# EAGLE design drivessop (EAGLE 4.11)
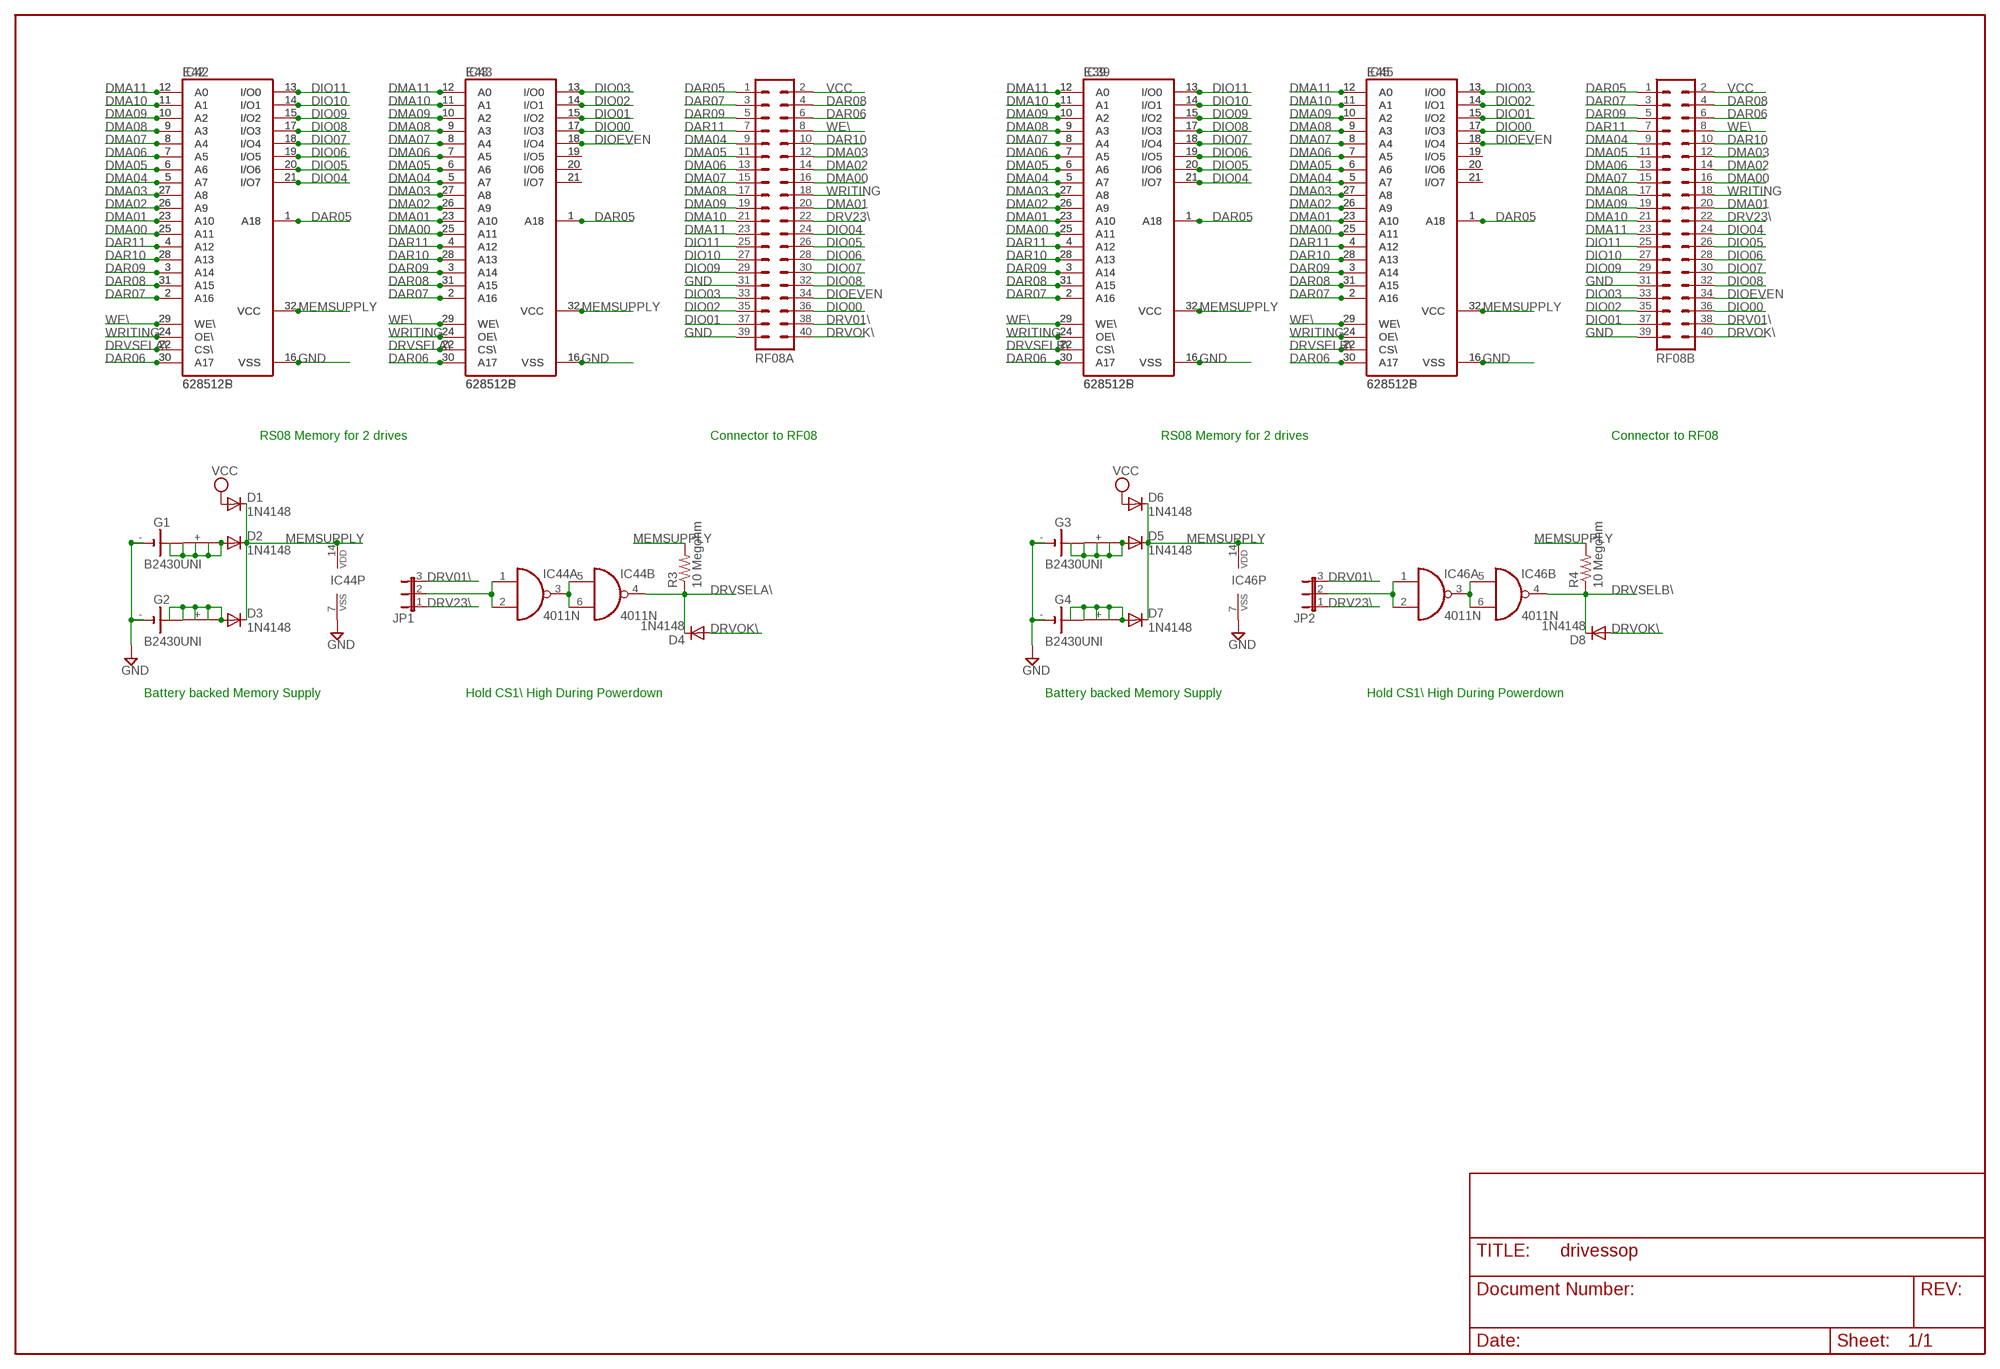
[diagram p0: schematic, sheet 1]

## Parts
D1  1N4148  [DO35-10]
D2  1N4148  [DO35-10]
D3  1N4148  [DO35-10]
D4  1N4148  [DO35-10]
D5  1N4148  [DO35-10]
D6  1N4148  [DO35-10]
D7  1N4148  [DO35-10]
D8  1N4148  [DO35-10]
E39  628512S  [S032L]
E42  628512S  [S032L]
E43  628512S  [S032L]
E45  628512S  [S032L]
G1  B2430UNI  [B2430UNI]
G2  B2430UNI  [B2430UNI]
G3  B2430UNI  [B2430UNI]
G4  B2430UNI  [B2430UNI]
IC39  628512P  [DIL32]
IC42  628512P  [DIL32]
IC43  628512P  [DIL32]
IC44  4011N  [DIL14]
IC45  628512P  [DIL32]
IC46  4011N  [DIL14]
JP1  JP2E  [JP2]
JP2  JP2E  [JP2]
R3  10 Megohm  R-US_0207/10  [0207/10]
R4  10 Megohm  R-US_0207/10  [0207/10]
RF08A  MA20-2  [MA20-2]
RF08B  MA20-2  [MA20-2]

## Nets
DAR05: E39.1(A18) E42.1(A18) E43.1(A18) E45.1(A18) IC39.1(A18) IC42.1(A18) IC43.1(A18) IC45.1(A18) RF08A.1 RF08B.1
DAR06: E39.30(A17) E42.30(A17) E43.30(A17) E45.30(A17) IC39.30(A17) IC42.30(A17) IC43.30(A17) IC45.30(A17) RF08A.6 RF08B.6
DAR07: E39.2(A16) E42.2(A16) E43.2(A16) E45.2(A16) IC39.2(A16) IC42.2(A16) IC43.2(A16) IC45.2(A16) RF08A.3 RF08B.3
DAR08: E39.31(A15) E42.31(A15) E43.31(A15) E45.31(A15) IC39.31(A15) IC42.31(A15) IC43.31(A15) IC45.31(A15) RF08A.4 RF08B.4
DAR09: E39.3(A14) E42.3(A14) E43.3(A14) E45.3(A14) IC39.3(A14) IC42.3(A14) IC43.3(A14) IC45.3(A14) RF08A.5 RF08B.5
DAR10: E39.28(A13) E42.28(A13) E43.28(A13) E45.28(A13) IC39.28(A13) IC42.28(A13) IC43.28(A13) IC45.28(A13) RF08A.10 RF08B.10
DAR11: E39.4(A12) E42.4(A12) E43.4(A12) E45.4(A12) IC39.4(A12) IC42.4(A12) IC43.4(A12) IC45.4(A12) RF08A.7 RF08B.7
DIO00: E43.17(I/O3) E45.17(I/O3) IC43.17(I/O3) IC45.17(I/O3) RF08A.36 RF08B.36
DIO01: E43.15(I/O2) E45.15(I/O2) IC43.15(I/O2) IC45.15(I/O2) RF08A.37 RF08B.37
DIO02: E43.14(I/O1) E45.14(I/O1) IC43.14(I/O1) IC45.14(I/O1) RF08A.35 RF08B.35
DIO03: E43.13(I/O0) E45.13(I/O0) IC43.13(I/O0) IC45.13(I/O0) RF08A.33 RF08B.33
DIO04: E39.21(I/O7) E42.21(I/O7) IC39.21(I/O7) IC42.21(I/O7) RF08A.24 RF08B.24
DIO05: E39.20(I/O6) E42.20(I/O6) IC39.20(I/O6) IC42.20(I/O6) RF08A.26 RF08B.26
DIO06: E39.19(I/O5) E42.19(I/O5) IC39.19(I/O5) IC42.19(I/O5) RF08A.28 RF08B.28
DIO07: E39.18(I/O4) E42.18(I/O4) IC39.18(I/O4) IC42.18(I/O4) RF08A.30 RF08B.30
DIO08: E39.17(I/O3) E42.17(I/O3) IC39.17(I/O3) IC42.17(I/O3) RF08A.32 RF08B.32
DIO09: E39.15(I/O2) E42.15(I/O2) IC39.15(I/O2) IC42.15(I/O2) RF08A.29 RF08B.29
DIO10: E39.14(I/O1) E42.14(I/O1) IC39.14(I/O1) IC42.14(I/O1) RF08A.27 RF08B.27
DIO11: E39.13(I/O0) E42.13(I/O0) IC39.13(I/O0) IC42.13(I/O0) RF08A.25 RF08B.25
DIOEVEN: E43.18(I/O4) E45.18(I/O4) IC43.18(I/O4) IC45.18(I/O4) RF08A.34 RF08B.34
DMA00: E39.25(A11) E42.25(A11) E43.25(A11) E45.25(A11) IC39.25(A11) IC42.25(A11) IC43.25(A11) IC45.25(A11) RF08A.16 RF08B.16
DMA01: E39.23(A10) E42.23(A10) E43.23(A10) E45.23(A10) IC39.23(A10) IC42.23(A10) IC43.23(A10) IC45.23(A10) RF08A.20 RF08B.20
DMA02: E39.26(A9) E42.26(A9) E43.26(A9) E45.26(A9) IC39.26(A9) IC42.26(A9) IC43.26(A9) IC45.26(A9) RF08A.14 RF08B.14
DMA03: E39.27(A8) E42.27(A8) E43.27(A8) E45.27(A8) IC39.27(A8) IC42.27(A8) IC43.27(A8) IC45.27(A8) RF08A.12 RF08B.12
DMA04: E39.5(A7) E42.5(A7) E43.5(A7) E45.5(A7) IC39.5(A7) IC42.5(A7) IC43.5(A7) IC45.5(A7) RF08A.9 RF08B.9
DMA05: E39.6(A6) E42.6(A6) E43.6(A6) E45.6(A6) IC39.6(A6) IC42.6(A6) IC43.6(A6) IC45.6(A6) RF08A.11 RF08B.11
DMA06: E39.7(A5) E42.7(A5) E43.7(A5) E45.7(A5) IC39.7(A5) IC42.7(A5) IC43.7(A5) IC45.7(A5) RF08A.13 RF08B.13
DMA07: E39.8(A4) E42.8(A4) E43.8(A4) E45.8(A4) IC39.8(A4) IC42.8(A4) IC43.8(A4) IC45.8(A4) RF08A.15 RF08B.15
DMA08: E39.9(A3) E42.9(A3) E43.9(A3) E45.9(A3) IC39.9(A3) IC42.9(A3) IC43.9(A3) IC45.9(A3) RF08A.17 RF08B.17
DMA09: E39.10(A2) E42.10(A2) E43.10(A2) E45.10(A2) IC39.10(A2) IC42.10(A2) IC43.10(A2) IC45.10(A2) RF08A.19 RF08B.19
DMA10: E39.11(A1) E42.11(A1) E43.11(A1) E45.11(A1) IC39.11(A1) IC42.11(A1) IC43.11(A1) IC45.11(A1) RF08A.21 RF08B.21
DMA11: E39.12(A0) E42.12(A0) E43.12(A0) E45.12(A0) IC39.12(A0) IC42.12(A0) IC43.12(A0) IC45.12(A0) RF08A.23 RF08B.23
DRV01\: JP1.3 JP2.3 RF08A.38 RF08B.38
DRV23\: JP1.1 JP2.1 RF08A.22 RF08B.22
DRVOK\: D4.A D8.A RF08A.40 RF08B.40
DRVSELA\: D4.C E42.22(CS\) E43.22(CS\) IC42.22(CS\) IC43.22(CS\) IC44.4(B:O) R3.1
DRVSELB\: D8.C E39.22(CS\) E45.22(CS\) IC39.22(CS\) IC45.22(CS\) IC46.4(B:O) R4.1
GND: E39.16(VSS) E42.16(VSS) E43.16(VSS) E45.16(VSS) G1.- G1.-@1(-) G2.- G2.-@1(-) G3.- G3.-@1(-) G4.- G4.-@1(-) IC39.16(VSS) IC42.16(VSS) IC43.16(VSS) IC44.7(P:VSS) IC45.16(VSS) IC46.7(P:VSS) RF08A.31 RF08A.39 RF08B.31 RF08B.39
MEMSUPPLY [Power]: D1.C D2.C D3.C D5.C D6.C D7.C E39.32(VCC) E42.32(VCC) E43.32(VCC) E45.32(VCC) IC39.32(VCC) IC42.32(VCC) IC43.32(VCC) IC44.14(P:VDD) IC45.32(VCC) IC46.14(P:VDD) R3.2 R4.2
N$1: E43.19(I/O5) IC43.19(I/O5)
N$2: E43.20(I/O6) IC43.20(I/O6)
N$3: E43.21(I/O7) IC43.21(I/O7)
N$4: E45.19(I/O5) IC45.19(I/O5)
N$5: E45.20(I/O6) IC45.20(I/O6)
N$6: E45.21(I/O7) IC45.21(I/O7)
N$18: IC44.3(A:O) IC44.5(B:I0) IC44.6(B:I1)
N$35: IC44.1(A:I0) IC44.2(A:I1) JP1.2
N$36: D7.A G4.+ G4.+@1(+) G4.+@2(+) G4.+@3(+) G4.+@4(+)
N$38: IC46.3(A:O) IC46.5(B:I0) IC46.6(B:I1)
N$39: IC46.1(A:I0) IC46.2(A:I1) JP2.2
N$41: D5.A G3.+ G3.+@1(+) G3.+@2(+) G3.+@3(+) G3.+@4(+)
N$130: D3.A G2.+ G2.+@1(+) G2.+@2(+) G2.+@3(+) G2.+@4(+)
N$131: D2.A G1.+ G1.+@1(+) G1.+@2(+) G1.+@3(+) G1.+@4(+)
VCC [Power]: D1.A D6.A RF08A.2 RF08B.2
WE\: E39.29(WE\) E42.29(WE\) E43.29(WE\) E45.29(WE\) IC39.29(WE\) IC42.29(WE\) IC43.29(WE\) IC45.29(WE\) RF08A.8 RF08B.8
WRITING: E39.24(OE\) E42.24(OE\) E43.24(OE\) E45.24(OE\) IC39.24(OE\) IC42.24(OE\) IC43.24(OE\) IC45.24(OE\) RF08A.18 RF08B.18
Unconnected: IC44.8(C:I0) IC44.9(C:I1) IC44.10(C:O) IC44.11(D:O) IC44.12(D:I0) IC44.13(D:I1) IC46.8(C:I0) IC46.9(C:I1) IC46.10(C:O) IC46.11(D:O) IC46.12(D:I0) IC46.13(D:I1)

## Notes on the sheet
- RS08 Memory for 2 drives | Connector to RF08 | RS08 Memory for 2 drives | Connector to RF08
- Battery backed Memory Supply | Hold CS1\ High During Powerdown | Battery backed Memory Supply | Hold CS1\ High During Powerdown

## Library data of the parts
D1-D8 = diode:1N4148: DIODE
E39 E42 E43 E45 = memory-hitachi:628512S: 512Kx8 Static RAM
G1-G4 = battery:B2430UNI: LI BATTERY
IC39 IC42 IC43 IC45 = memory-hitachi:628512P: 512Kx8 Static RAM
IC44 IC46 = 40xx:4011: Quad 2-input NAND
JP1 JP2 = jumper:JP2E: JUMPER
R3 R4 = rcl:R-US_: RESISTOR, American symbol
RF08A RF08B = con-lstb:MA20-2: PIN HEADER

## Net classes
1 Power: width 0.508 mm

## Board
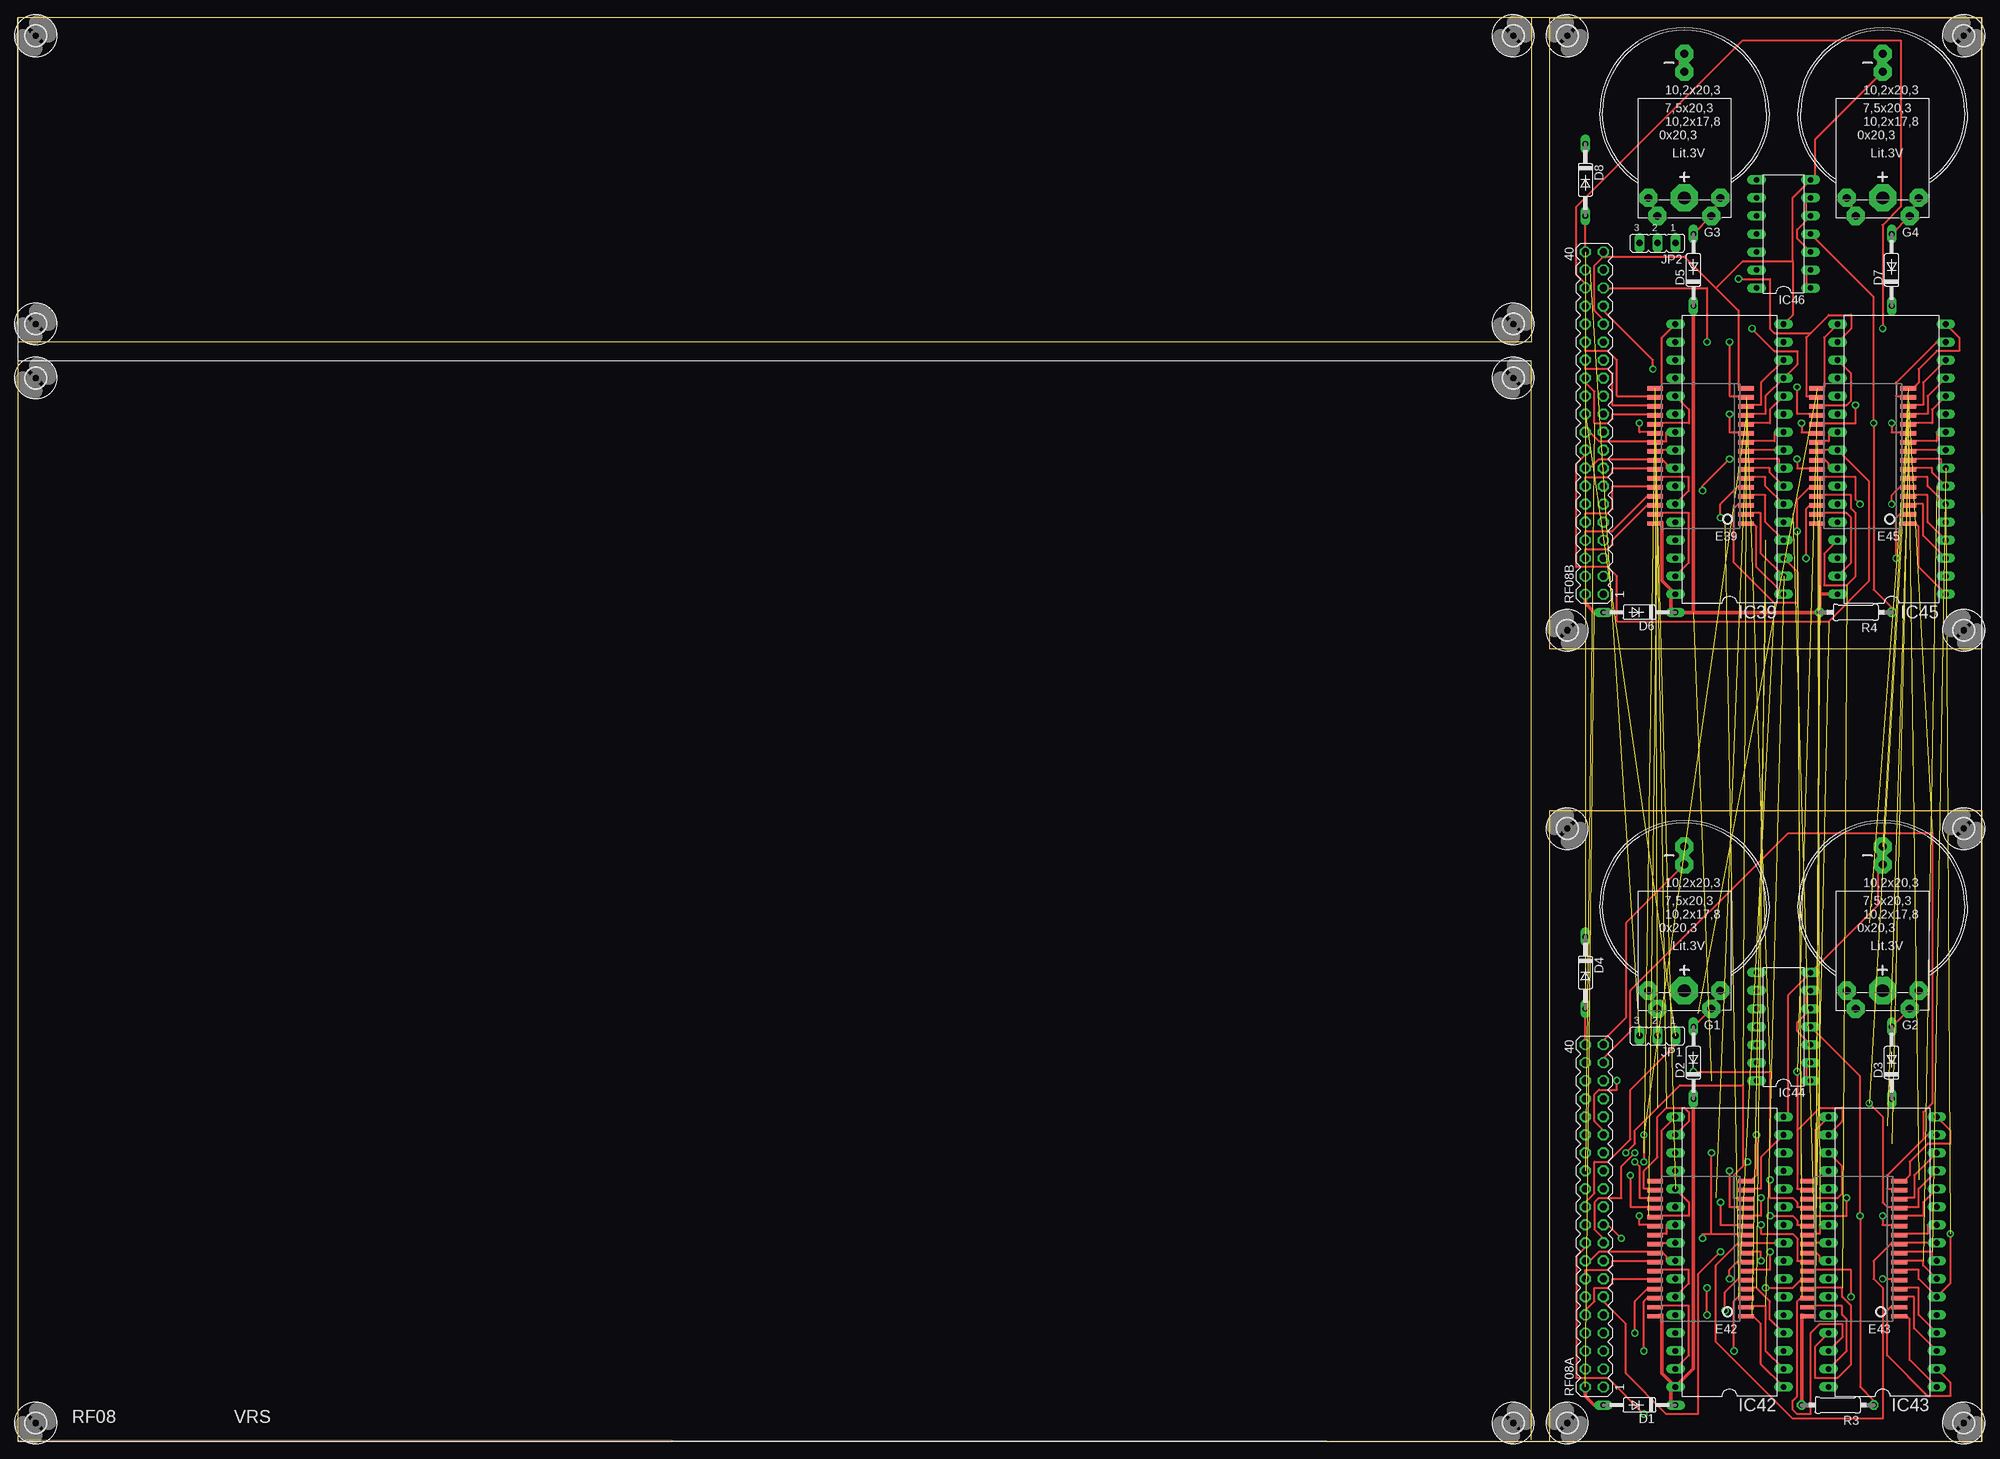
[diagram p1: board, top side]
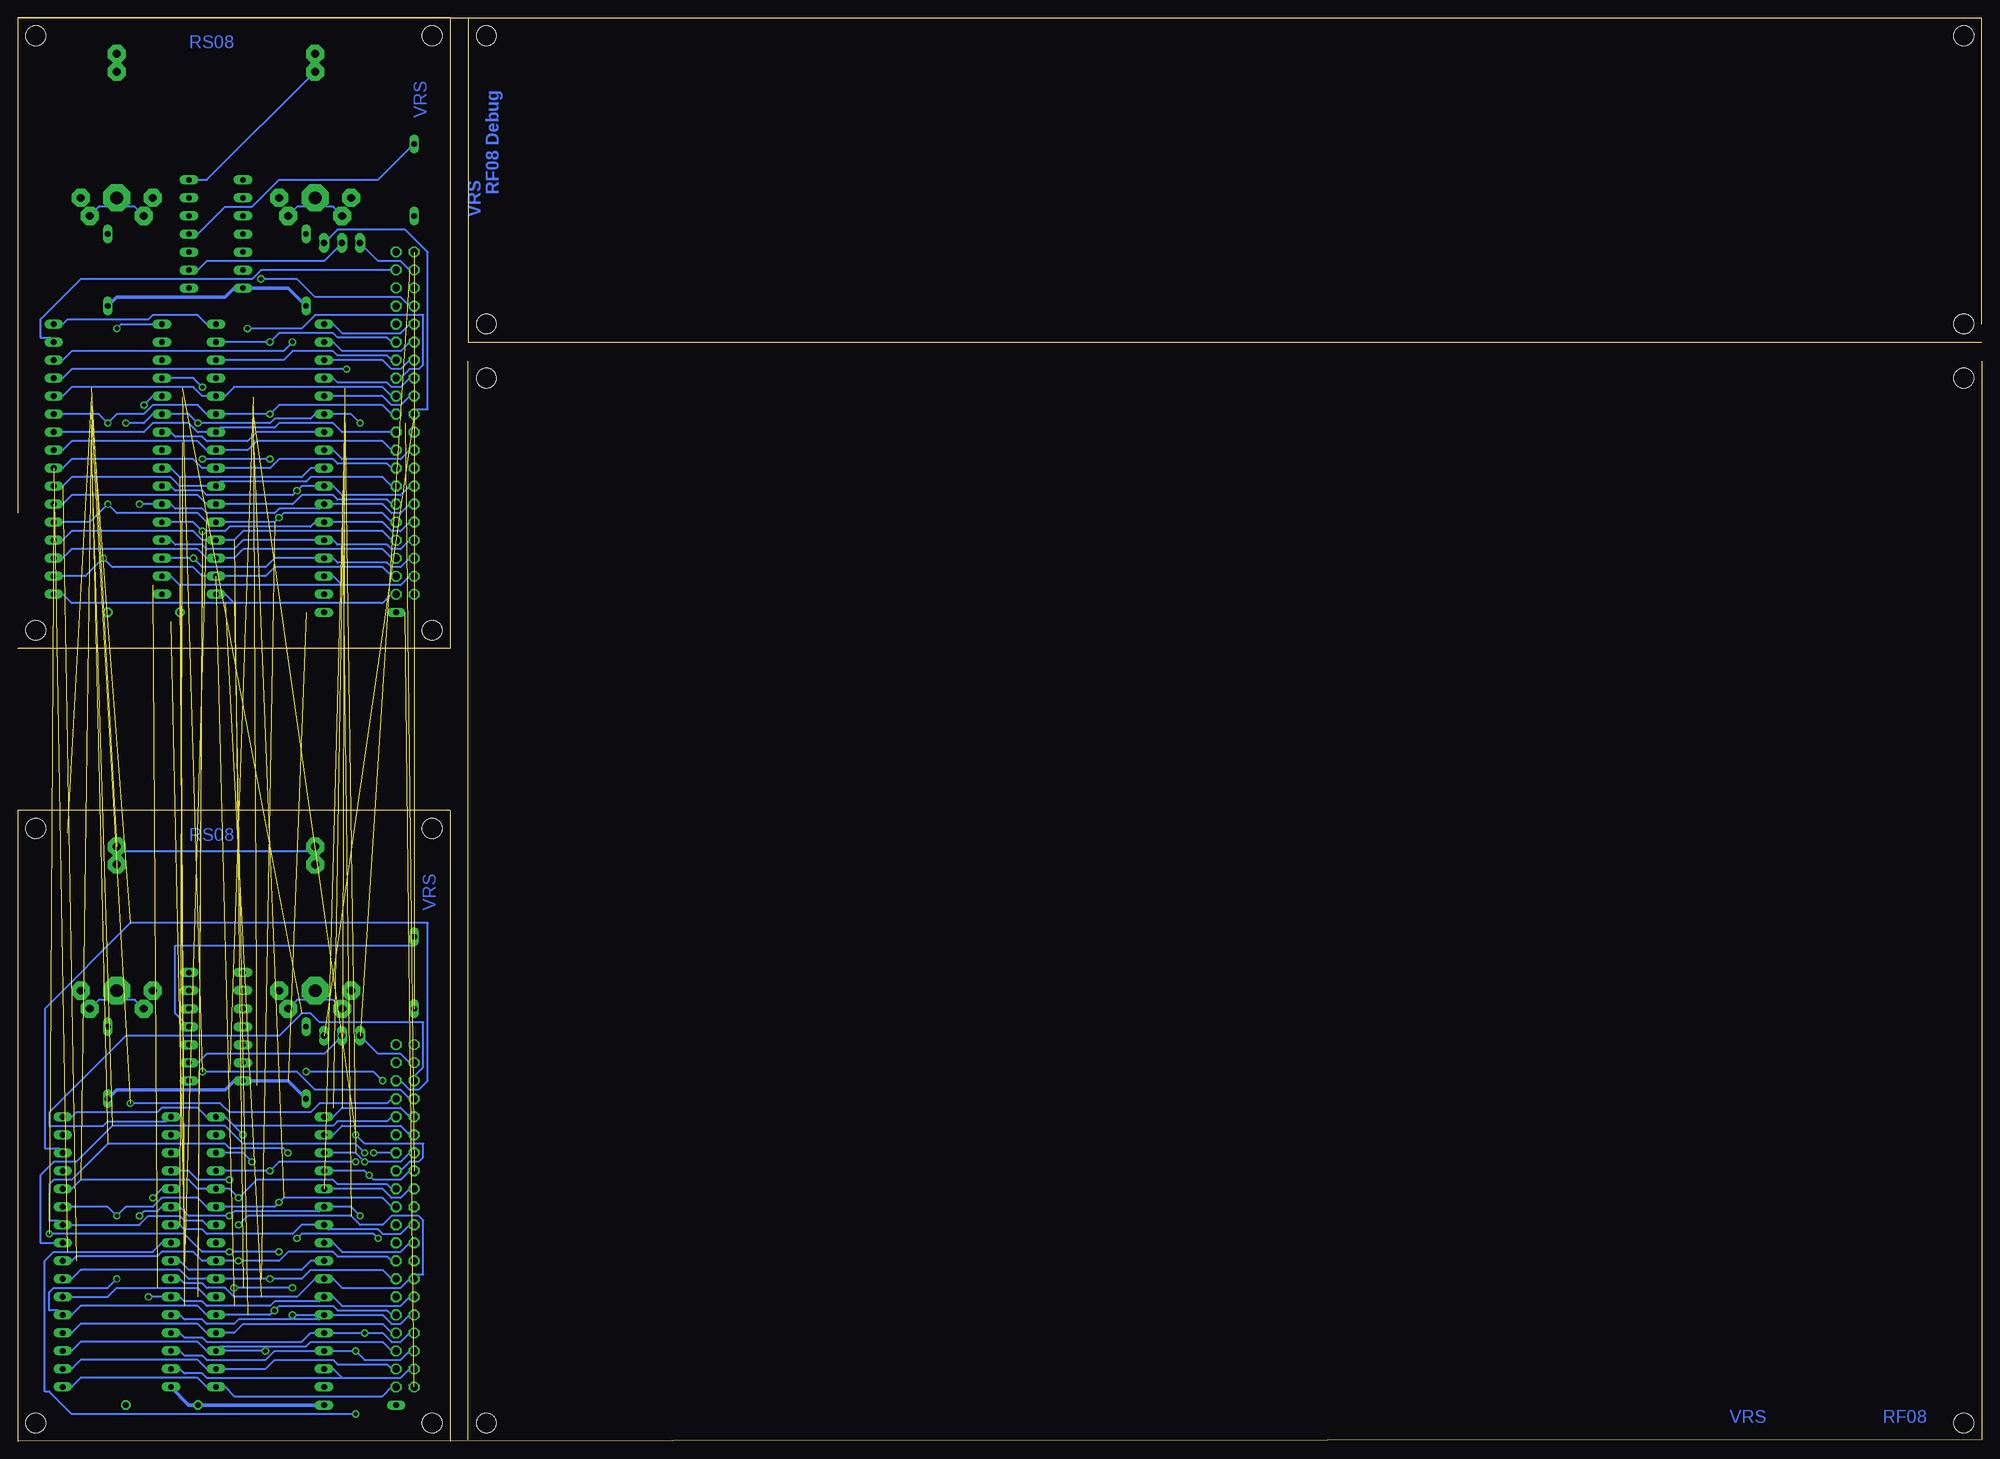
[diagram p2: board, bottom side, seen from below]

Size 276.86 x 200.67 mm. Coordinates in mm from the lower left corner, seen from the top.
Outline: 276.69,0 0.01,0.18 0.01,152.25
Outline: 213.34,0.18 213.34,152.25
Outline: 215.9,0.01 215.9,88.92 276.86,88.92 276.86,0.01
Outline: 276.86,111.78 215.9,111.78 215.9,200.67 276.86,200.67
Outline: 276.86,200.67 0,200.67 0,157.49
Outline: 276.86,200.67 276.86,130.82
Outline: 0,154.95 213.36,154.95 213.36,200.67
Copper layers (1*16): Top 0.035mm / dielectric 1.5mm / Bottom 0.035mm
Design rules "olimex10mil": minimum track width 10mil, minimum drill 24mil, track to track 10mil, track to pad 10mil, pad to pad 10mil, via to via 10mil, smd to smd 10mil, copper to edge 40mil, drill to drill 10mil, minimum pad ring 10mil, minimum via ring 8mil, stop-mask expansion 0mil, vias tented up to drill 0mil, thermal gap 10mil

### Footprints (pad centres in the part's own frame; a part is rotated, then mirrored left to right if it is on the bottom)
DO35-10 = drill 0.813 long: A 5.08,0; C -5.08,0
S032L = smd 0.6 x 2.2: 1 -7.795,-6.146; 2 -6.525,-6.146; 3 -5.255,-6.146; 4 -3.985,-6.146; 5 -2.715,-6.146; 6 -1.445,-6.146; 7 -0.175,-6.146; 8 1.095,-6.146; 9 2.365,-6.146; 10 3.635,-6.146; 11 4.905,-6.146; 12 6.175,-6.146; 13 7.445,-6.146; 14 8.715,-6.146; 15 9.985,-6.146; 16 11.255,-6.146; 17 11.255,6.686; 18 9.985,6.686; 19 8.715,6.686; 20 7.445,6.686; 21 6.175,6.686; 22 4.905,6.686; 23 3.635,6.686; 24 2.365,6.686; 25 1.095,6.686; 26 -0.175,6.686; 27 -1.445,6.686; 28 -2.715,6.686; 29 -3.985,6.686; 30 -5.255,6.686; 31 -6.525,6.686; 32 -7.795,6.686
B2430UNI = drill 1.118 pad 2.54 octagon: + 3.81,14.605; +@1 -3.81,14.605; +@2 -5.08,12.065; +@3 5.08,12.065; - 0,-5.715; -@1 0,-8.255 | drill 1.803 pad 3.81 octagon: +@4 0,12.065
DIL32 = drill 0.813 long: 1 -19.05,-7.62; 2 -16.51,-7.62; 3 -13.97,-7.62; 4 -11.43,-7.62; 5 -8.89,-7.62; 6 -6.35,-7.62; 7 -3.81,-7.62; 8 -1.27,-7.62; 9 1.27,-7.62; 10 3.81,-7.62; 11 6.35,-7.62; 12 8.89,-7.62; 13 11.43,-7.62; 14 13.97,-7.62; 15 16.51,-7.62; 16 19.05,-7.62; 17 19.05,7.62; 18 16.51,7.62; 19 13.97,7.62; 20 11.43,7.62; 21 8.89,7.62; 22 6.35,7.62; 23 3.81,7.62; 24 1.27,7.62; 25 -1.27,7.62; 26 -3.81,7.62; 27 -6.35,7.62; 28 -8.89,7.62; 29 -11.43,7.62; 30 -13.97,7.62; 31 -16.51,7.62; 32 -19.05,7.62
DIL14 = drill 0.813 long: 1 -7.62,-3.81; 2 -5.08,-3.81; 3 -2.54,-3.81; 4 0,-3.81; 5 2.54,-3.81; 6 5.08,-3.81; 7 7.62,-3.81; 8 7.62,3.81; 9 5.08,3.81; 10 2.54,3.81; 11 0,3.81; 12 -2.54,3.81; 13 -5.08,3.81; 14 -7.62,3.81
JP2 = drill 0.914 long: 1 -2.54,0; 2 0,0; 3 2.54,0
0207/10 = drill 0.813 octagon: 1 -5.08,0; 2 5.08,0
MA20-2 = drill 1.016 octagon: 1 -24.13,-1.27; 2 -24.13,1.27; 3 -21.59,-1.27; 4 -21.59,1.27; 5 -19.05,-1.27; 6 -19.05,1.27; 7 -16.51,-1.27; 8 -16.51,1.27; 9 -13.97,-1.27; 10 -13.97,1.27; 11 -11.43,-1.27; 12 -11.43,1.27; 13 -8.89,-1.27; 14 -8.89,1.27; 15 -6.35,-1.27; 16 -6.35,1.27; 17 -3.81,-1.27; 18 -3.81,1.27; 19 -1.27,-1.27; 20 -1.27,1.27; 21 1.27,-1.27; 22 1.27,1.27; 23 3.81,-1.27; 24 3.81,1.27; 25 6.35,-1.27; 26 6.35,1.27; 27 8.89,-1.27; 28 8.89,1.27; 29 11.43,-1.27; 30 11.43,1.27; 31 13.97,-1.27; 32 13.97,1.27; 33 16.51,-1.27; 34 16.51,1.27; 35 19.05,-1.27; 36 19.05,1.27; 37 21.59,-1.27; 38 21.59,1.27; 39 24.13,-1.27; 40 24.13,1.27
2,8 = hole 2.8: 0,0

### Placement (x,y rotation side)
D1  228.6,5.09 180 top
D2  236.22,53.36 90 top
D3  264.16,53.36 90 top
D4  220.98,66.06 270 top
D5  236.22,165.11 90 top
D6  228.6,116.86 180 top
D7  264.16,165.11 90 top
D8  220.98,177.81 270 top
E39  237.49,137.17 90 top
E42  237.49,25.41 90 top
E43  259.08,25.41 90 top
E45  260.35,137.17 90 top
G1  234.95,75.58 180 top
G2  262.89,75.58 180 top
G3  234.95,187.34 180 top
G4  262.89,187.34 180 top
IC39  241.3,138.44 90 top
IC42  241.3,26.69 90 top
IC43  262.89,26.69 90 top
IC44  248.92,58.44 90 top
IC45  264.16,138.44 90 top
IC46  248.92,170.19 90 top
JP1  231.14,57.16 180 top
JP2  231.14,168.92 180 top
R3  256.54,5.09 180 top
R4  259.08,116.86 180 top
RF08A  222.25,31.77 90 top
RF08B  222.25,143.52 90 top
U$1  [2,8]  2.54,149.88 0 top
U$2  [2,8]  210.82,149.88 0 top
U$3  [2,8]  2.54,2.56 0 top
U$4  [2,8]  210.82,2.56 0 top
U$5  [2,8]  274.32,2.56 90 top
U$6  [2,8]  218.44,2.56 90 top
U$7  [2,8]  218.44,86.38 90 top
U$8  [2,8]  274.32,86.38 90 top
U$9  [2,8]  274.32,198.13 90 top
U$10  [2,8]  274.32,114.31 90 top
U$11  [2,8]  218.44,114.31 90 top
U$12  [2,8]  218.44,198.13 90 top
U$13  [2,8]  2.54,157.49 0 top
U$14  [2,8]  2.54,198.13 0 top
U$16  [2,8]  210.82,157.49 0 top
U$17  [2,8]  210.82,198.13 0 top
U$18  [SIERRA-PROTO]  0,0.01 0 top

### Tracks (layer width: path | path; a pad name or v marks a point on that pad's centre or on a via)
DAR05  (1 unrouted)
  Top 0.254: E43.1 266.06,17.8 266.7,17.16 266.7,11.45 IC43.1 | E42.1 244.47,17.8 245.75,16.53 245.75,10.81 IC42.1 | E45.1 267.33,129.55 267.97,128.92 267.97,123.2 IC45.1 | E39.1 244.47,129.55 245.11,128.92 245.11,123.2 IC39.1
  Bottom 0.254: RF08A.1 224.16,7.63 225.43,6.36 246.38,6.36 247.65,7.63 IC42.1 250.19,7.63 251.46,8.91 267.97,8.91 269.24,7.63 IC43.1 | 246.38,118.12 225.43,118.12 224.16,119.39 RF08B.1 | 246.38,118.12 247.65,119.39 IC39.1 | 246.38,118.12 269.24,118.12 270.51,119.39 IC45.1
DAR06  (via drill 0.61)  (1 unrouted)
  Top 0.254: E43.30 251.46,20.34 250.82,19.7 250.82,6.36 250.19,5.73 250.19,4.46 250.82,3.83 252.73,3.83 252.73,15.26 254,16.53 257.18,16.53 257.18,14.62 IC43.30 | v229.24,12.71 229.24,19.7 229.87,20.34 E42.30 | v252.09,124.47 252.09,131.46 252.73,132.09 E45.30 | E39.30 229.87,132.09 224.79,127.02 224.79,126.38 224.16,125.75 220.98,125.75 RF08B.6
  Bottom 0.254: RF08A.6 221.62,12.71 222.88,11.45 227.97,11.45 v229.24,12.71 IC42.30 240.66,12.71 241.94,11.45 250.19,11.45 250.82,12.08 253.37,12.08 254,12.71 IC43.30 | IC45.30 v252.09,124.47 250.82,123.2 241.94,123.2 240.66,124.47 IC39.30 232.41,124.47 231.78,123.84 224.79,123.84 224.16,123.2 222.88,123.2 221.62,124.47 RF08B.6
DAR07  (via drill 0.61)  (1 unrouted)
  Top 0.254: E43.2 264.16,19.07 263.52,18.43 263.52,12.08 269.24,6.36 272.42,6.36 272.42,8.27 IC43.2 | E42.2 244.47,19.07 246.38,19.07 246.38,12.71 IC42.2 | v264.8,124.47 264.8,130.19 265.43,130.82 E45.2 | E39.2 244.47,130.82 245.75,130.82 245.75,125.11 IC39.2
  Bottom 0.254: RF08A.3 224.16,10.18 224.79,10.81 231.78,10.81 232.41,11.45 240.66,11.45 241.94,10.18 IC42.2 250.19,10.18 251.46,11.45 267.97,11.45 269.24,10.18 IC43.2 | IC45.2 267.33,121.94 v264.8,124.47 263.52,123.2 252.09,123.2 250.82,121.94 IC39.2 241.94,121.94 240.66,123.2 225.43,123.2 224.16,121.94 RF08B.3
DAR08  (1 unrouted)
  Top 0.254: E43.31 253.37,19.07 257.18,19.07 257.18,17.8 257.81,17.16 257.81,12.71 IC43.31 | E42.31 231.78,19.07 235.59,19.07 235.59,12.08 IC42.31 | E45.31 254.63,130.82 257.81,130.82 258.44,130.19 258.44,123.84 IC45.31 | E39.31 231.78,130.82 235.59,130.82 235.59,123.84 IC39.31
  Bottom 0.254: 231.14,8.91 222.88,8.91 221.62,10.18 RF08A.4 | 231.14,8.91 232.41,10.18 IC42.31 | 231.14,8.91 250.19,8.91 250.82,9.54 253.37,9.54 254,10.18 IC43.31 | 231.14,120.67 222.88,120.67 221.62,121.94 RF08B.4 | 231.14,120.67 232.41,121.94 IC39.31 | 231.14,120.67 254,120.67 255.27,121.94 IC45.31
DAR09  (via drill 0.61)  (1 unrouted)
  Top 0.254: E43.3 266.06,20.34 267.33,20.34 267.33,15.89 IC43.3 | v241.94,12.71 241.94,19.7 242.57,20.34 E42.3 | E45.3 267.33,132.09 268.61,132.09 268.61,127.65 IC45.3 | E39.3 242.57,132.09 241.94,131.46 241.94,123.84 247.65,118.12 250.82,118.12 250.82,122.57 IC39.3
  Bottom 0.254: v241.94,12.71 IC42.3 | RF08A.5 224.16,12.71 225.43,13.99 235.59,13.99 236.22,13.35 248.28,13.35 IC42.3 | IC43.3 269.24,12.71 267.97,13.99 251.46,13.99 250.19,12.71 IC42.3 | RF08B.5 224.16,124.47 225.43,125.75 245.11,125.75 246.38,124.47 IC39.3 250.19,124.47 251.46,125.75 269.24,125.75 270.51,124.47 IC45.3
DAR10  (via drill 0.61)  (1 unrouted)
  Top 0.254: E42.28 229.87,22.88 224.79,22.88 224.79,22.24 224.16,21.61 222.25,21.61 222.25,19.7 220.98,18.43 RF08A.10 | v246.38,21.61 250.19,21.61 251.46,22.88 E43.28 | v238.12,17.8 v238.12,21.61 | E39.28 229.87,134.63 224.79,134.63 224.79,131.46 224.16,130.82 220.98,130.82 RF08B.10 | v250.82,128.28 250.82,132.73 252.73,134.63 E45.28
  Bottom 0.254: v238.12,21.61 v246.38,21.61 | v238.12,17.8 IC42.28 | IC43.28 254,17.8 253.37,17.16 250.82,17.16 250.19,16.53 246.38,16.53 245.75,17.16 234.31,17.16 IC42.28 | RF08A.10 221.62,17.8 222.88,16.53 224.16,16.53 225.43,17.8 IC42.28 | IC45.28 252.09,129.55 v250.82,128.28 247.65,128.28 247.01,128.92 235.59,128.92 234.95,129.55 IC39.28 225.43,129.55 224.16,128.28 222.88,128.28 221.62,129.55 RF08B.10
DAR11  (1 unrouted)
  Top 0.254: E45.4 267.33,133.36 269.24,133.36 269.24,129.55 IC45.4 | E39.4 244.47,133.36 246.38,133.36 246.38,129.55 IC39.4 | E43.4 266.06,21.61 267.97,21.61 267.97,17.8 IC43.4 | E42.4 244.47,21.61 245.11,21.61 247.01,19.7 247.01,17.16 IC42.4
  Bottom 0.254: RF08B.7 224.16,127.02 225.43,128.28 245.11,128.28 246.38,127.02 IC39.4 250.82,127.02 252.09,128.28 269.24,128.28 270.51,127.02 IC45.4 | RF08A.7 224.16,15.26 225.43,16.53 245.11,16.53 246.38,15.26 IC42.4 250.19,15.26 251.46,16.53 267.97,16.53 269.24,15.26 IC43.4
DIO00  (via drill 0.61)  (1 unrouted)
  Top 0.254: E43.17 253.37,36.84 253.37,43.83 IC43.17 | E45.17 254.63,148.6 254.63,155.59 IC45.17 | v262.89,156.86 262.89,171.46 265.43,174 265.43,197.5 243.21,197.5 219.71,174 219.71,164.48 220.98,163.21 RF08B.36
  Bottom 0.254: RF08A.36 220.98,51.45 219.71,52.72 219.71,59.07 234.31,59.07 235.59,60.34 236.85,60.34 240.03,57.16 261.62,57.16 272.42,46.37 272.42,44.47 264.8,44.47 264.16,45.1 255.91,45.1 IC43.17 | v262.89,156.86 262.25,157.49 IC45.17
DIO01  (1 unrouted)
  Top 0.254: 268.61,42.56 269.24,43.2 IC43.15 | 268.61,42.56 263.52,37.48 263.52,35.58 264.16,35.58 E43.15 | 268.61,42.56 268.61,46.37 269.88,47.64 269.88,85.74 249.56,85.74 227.33,63.52 227.33,57.8 223.52,53.99 RF08A.37 | E45.15 265.43,147.33 264.8,147.33 264.8,149.24 270.51,154.95 IC45.15
  Bottom 0.254: RF08B.37 242.57,165.11 243.84,163.84 267.97,163.84 273.69,158.13 273.69,155.59 272.42,155.59 IC45.15
DIO02  (via drill 0.61)  (1 unrouted)
  Top 0.254: E43.14 266.06,34.3 267.33,34.3 267.33,37.48 IC43.14 | E45.14 267.33,146.06 268.61,146.06 268.61,149.24 IC45.14 | v238.12,154.95 238.12,162.57 RF08B.35
  Bottom 0.254: RF08A.35 222.88,50.81 221.62,49.55 220.34,49.55 219.07,50.81 219.07,73.04 260.99,73.04 273.05,60.98 273.05,41.29 271.14,41.29 IC43.14 | v238.12,154.95 239.4,153.68 269.24,153.68 270.51,152.41 IC45.14
DIO03  (via drill 0.61)  (1 unrouted)
  Top 0.254: IC43.13 267.97,35.58 267.97,33.04 266.06,33.04 E43.13 264.16,33.04 263.52,33.04 262.89,33.67 262.89,45.73 v260.99,47.64 | E45.13 267.33,144.79 269.24,144.79 269.24,147.33 IC45.13 | v230.5,151.14 230.5,152.41 223.52,159.4 RF08B.33
  Bottom 0.254: v260.99,47.64 248.28,47.64 247.01,46.37 235.59,46.37 234.31,47.64 224.79,47.64 224.16,48.27 RF08A.33 | v230.5,151.14 269.24,151.14 270.51,149.88 IC45.13
DIO04  (1 unrouted)
  Top 0.254: E42.21 231.78,31.77 235.59,31.77 235.59,33.67 IC42.21 | E39.21 231.78,143.52 235.59,143.52 235.59,145.43 IC39.21
  Bottom 0.254: RF08A.24 221.62,35.58 222.88,34.3 224.16,34.3 225.43,35.58 IC42.21 | RF08B.24 221.62,147.33 222.88,146.06 224.16,146.06 225.43,147.33 IC39.21
DIO05  (via drill 0.61)  (1 unrouted)
  Top 0.254: E39.20 229.87,144.79 224.79,144.79 224.79,144.16 224.16,143.52 222.25,143.52 222.25,147.97 220.98,149.24 RF08B.26 | v227.33,37.48 227.33,33.04 229.87,33.04 E42.20
  Bottom 0.254: IC39.20 232.41,149.88 231.78,149.24 224.79,149.24 224.16,148.6 222.88,148.6 221.62,149.88 RF08B.26 | IC42.20 227.97,38.12 v227.33,37.48 226.69,36.84 222.88,36.84 221.62,38.12 RF08A.26
DIO06  (via drill 0.61)  (1 unrouted)
  Top 0.254: v227.97,39.38 228.6,38.75 228.6,34.3 229.87,34.3 E42.19 | E39.19 229.87,146.06 224.79,146.06 224.79,150.51 224.16,151.14 220.98,151.14 RF08B.28
  Bottom 0.254: IC42.19 229.24,40.66 v227.97,39.38 222.88,39.38 221.62,40.66 RF08A.28 | IC39.19 225.43,152.41 224.16,151.14 222.88,151.14 221.62,152.41 RF08B.28
DIO07  (1 unrouted)
  Top 0.254: E42.18 229.87,35.58 229.24,35.58 229.24,38.12 231.14,40.02 231.14,45.73 232.41,47.01 234.95,47.01 235.59,46.37 235.59,45.1 IC42.18 | E39.18 229.87,147.33 225.43,147.33 225.43,152.41 224.16,153.68 220.98,153.68 RF08B.30
  Bottom 0.254: RF08A.30 221.62,43.2 222.88,44.47 231.14,44.47 232.41,43.2 IC42.18 | IC39.18 232.41,154.95 231.14,153.68 222.88,153.68 221.62,154.95 RF08B.30
DIO08  (1 unrouted)
  Top 0.254: E42.17 231.78,36.84 231.78,43.83 IC42.17 | E39.17 231.78,148.6 231.78,155.59 IC39.17
  Bottom 0.254: RF08A.32 221.62,45.73 222.88,47.01 231.14,47.01 232.41,45.73 IC42.17 | RF08B.32 221.62,157.49 222.88,156.22 231.14,156.22 232.41,157.49 IC39.17
DIO09  (via drill 0.61)  (1 unrouted)
  Top 0.254: 247.01,41.29 245.75,40.02 245.75,35.58 244.47,35.58 E42.15 | 247.01,41.29 IC42.15 | v225.43,50.81 225.43,49.55 222.88,49.55 222.25,48.91 222.25,45.1 223.52,43.83 RF08A.29 | v236.22,52.09 247.01,52.09 247.01,41.29 | v241.3,154.95 241.3,147.33 242.57,147.33 E39.15
  Bottom 0.254: v225.43,50.81 226.69,52.09 v236.22,52.09 | IC39.15 v241.3,154.95 240.03,156.22 232.41,156.22 231.78,155.59 224.79,155.59 224.16,154.95 RF08B.29
DIO10  (via drill 0.61)  (1 unrouted)
  Top 0.254: 243.21,38.75 v243.84,39.38 | 243.21,38.75 241.94,37.48 241.94,34.3 242.57,34.3 E42.14 | v226.69,40.66 227.97,41.92 227.97,43.83 234.31,50.18 243.21,50.18 243.21,38.75 | E39.14 244.47,146.06 245.75,146.06 245.75,149.24 IC39.14
  Bottom 0.254: v243.84,39.38 245.11,40.66 IC42.14 | RF08A.27 v226.69,40.66 | RF08B.27 224.16,152.41 224.79,153.05 231.78,153.05 232.41,153.68 238.12,153.68 239.4,152.41 IC39.14
DIO11  (via drill 0.61)  (1 unrouted)
  Top 0.254: v241.3,38.12 241.3,33.04 242.57,33.04 E42.13 | v229.24,43.2 v229.24,39.38 | E39.13 244.47,144.79 246.38,144.79 246.38,147.33 IC39.13 250.82,151.78 250.82,153.68 247.65,153.68 v244.47,156.86
  Bottom 0.254: IC42.13 v241.3,38.12 240.03,39.38 v229.24,39.38 | v229.24,43.2 227.97,41.92 219.71,41.92 219.71,40.02 220.34,39.38 221.62,39.38 222.88,38.12 RF08A.25 | v244.47,156.86 236.85,156.86 234.95,158.76 219.71,158.76 219.71,151.78 220.34,151.14 221.62,151.14 222.88,149.88 RF08B.25
DIOEVEN  (via drill 0.61)  (1 unrouted)
  Top 0.254: 250.82,43.83 250.82,35.58 251.46,35.58 E43.18 | 250.82,43.83 254,47.01 257.18,47.01 257.18,45.1 IC43.18 | v250.82,52.09 250.82,43.83 | 252.73,156.22 255.27,158.76 258.44,158.76 258.44,156.86 IC45.18 | 252.73,156.22 252.09,155.59 252.09,147.33 252.73,147.33 E45.18 | v242.57,163.84 247.01,163.84 247.01,156.86 247.65,156.22 252.73,156.22
  Bottom 0.254: v250.82,52.09 237.49,52.09 234.95,49.55 222.88,49.55 221.62,48.27 RF08A.34 | v242.57,163.84 237.49,163.84 234.95,161.3 222.88,161.3 221.62,160.03 RF08B.34
DMA00  (1 unrouted)
  Top 0.254: E43.25 253.37,26.69 254,26.05 254,25.41 IC43.25 | IC42.25 232.41,25.41 232.41,26.05 231.78,26.69 E42.25 229.87,26.69 222.88,26.69 221.62,25.41 RF08A.16 | E45.25 254.63,138.44 255.27,137.81 255.27,137.17 IC45.25 | IC39.25 232.41,137.17 232.41,137.81 231.78,138.44 E39.25 229.87,138.44 222.88,138.44 221.62,137.17 RF08B.16
  Bottom 0.254: IC43.25 254,25.41 252.73,24.14 236.85,24.14 235.59,25.41 IC42.25 | IC45.25 255.27,137.17 254,135.9 236.85,135.9 235.59,137.17 IC39.25
DMA01  (1 unrouted)
  Top 0.254: E43.23 253.37,29.23 254,29.23 254,30.5 IC43.23 | E42.23 231.78,29.23 232.41,29.23 232.41,30.5 IC42.23 | E45.23 254.63,140.98 255.27,140.98 255.27,142.25 IC45.23 | IC39.23 232.41,142.25 232.41,140.98 231.78,140.98 E39.23 229.87,140.98 222.88,140.98 221.62,142.25 RF08B.20
  Bottom 0.254: RF08A.20 221.62,30.5 222.88,29.23 225.43,29.23 226.06,29.86 233.04,29.86 IC42.23 236.85,30.5 238.12,29.23 250.19,29.23 250.82,29.86 253.37,29.86 254,30.5 IC43.23 | IC45.23 255.27,142.25 254.63,141.62 250.82,141.62 250.19,140.98 244.47,140.98 243.21,142.25 IC39.23
DMA02  (via drill 0.61)  (1 unrouted)
  Top 0.254: E39.26 229.87,137.17 224.79,137.17 224.79,136.54 224.16,135.9 220.98,135.9 RF08B.14 | v250.82,138.44 250.82,137.17 252.73,137.17 E45.26 | v241.3,138.44 237.49,134.63 v237.49,134 | E42.26 229.87,25.41 224.79,25.41 224.79,24.78 224.16,24.14 220.98,24.14 RF08A.14 | v245.75,30.5 245.75,29.23 250.19,29.23 250.82,28.59 250.82,25.41 251.46,25.41 E43.26
  Bottom 0.254: v241.3,138.44 v250.82,138.44 | IC45.26 255.27,134.63 254.63,134 250.82,134 250.19,133.36 238.12,133.36 v237.49,134 236.85,134.63 IC39.26 232.41,134.63 231.14,133.36 222.88,133.36 221.62,134.63 RF08B.14 | v245.75,30.5 244.47,31.77 229.87,31.77 228.6,30.5 225.43,30.5 224.16,31.77 220.34,31.77 219.71,31.13 219.71,23.51 220.98,23.51 RF08A.14 221.62,22.88 222.88,21.61 231.14,21.61 232.41,22.88 IC42.26 234.95,22.88 237.49,20.34 246.38,20.34 247.65,21.61 250.19,21.61 250.82,22.24 253.37,22.24 254,22.88 IC43.26
DMA03  (via drill 0.61)  (1 unrouted)
  Top 0.254: v258.44,20.34 258.44,24.14 253.37,24.14 E43.27 | E42.27 231.78,24.14 235.59,24.14 235.59,22.24 IC42.27 | v259.71,132.09 259.08,132.73 259.08,135.9 254.63,135.9 E45.27 | E39.27 231.78,135.9 235.59,135.9 235.59,134 IC39.27
  Bottom 0.254: v258.44,20.34 IC43.27 254,20.34 253.37,19.7 250.82,19.7 250.19,19.07 241.3,19.07 240.66,19.7 234.31,19.7 IC42.27 232.41,20.34 231.14,19.07 222.88,19.07 221.62,20.34 RF08A.12 | v259.71,132.09 IC45.27 255.27,132.09 254.63,131.46 250.82,131.46 250.19,130.82 240.66,130.82 240.03,131.46 234.31,131.46 IC39.27 225.43,132.09 224.16,130.82 222.88,130.82 221.62,132.09 RF08B.12
DMA04  (via drill 0.61)  (1 unrouted)
  Top 0.254: v264.16,132.09 264.16,133.36 265.43,134.63 E45.5 | v240.03,130.19 240.03,132.09 242.57,134.63 E39.5 | v262.89,22.88 264.16,22.88 E43.5 | v240.66,18.43 240.66,20.97 242.57,22.88 E42.5
  Bottom 0.254: IC45.5 266.7,129.55 v264.16,132.09 262.89,130.82 251.46,130.82 250.19,129.55 IC39.5 240.66,129.55 v240.03,130.19 239.4,130.82 225.43,130.82 224.16,129.55 RF08B.9 | v262.89,22.88 264.16,21.61 271.78,21.61 272.42,20.97 272.42,18.43 271.14,18.43 IC43.5 269.24,17.8 267.97,19.07 251.46,19.07 250.19,17.8 IC42.5 241.3,17.8 v240.66,18.43 240.03,19.07 232.41,19.07 231.78,18.43 224.79,18.43 224.16,17.8 RF08A.9
DMA05  (via drill 0.61)  (1 unrouted)
  Top 0.254: v247.01,26.69 247.01,24.14 244.47,24.14 E42.6 | v272.42,29.23 272.42,22.24 IC43.6 267.97,22.88 267.97,24.14 266.06,24.14 E43.6 | v240.03,26.69 236.85,23.51 236.85,3.83 232.41,3.83 226.69,9.54 226.69,16.53 223.52,19.7 RF08A.11 | E45.6 267.33,135.9 269.24,135.9 269.24,134.63 IC45.6 | E39.6 244.47,135.9 246.38,135.9 246.38,134.63 IC39.6
  Bottom 0.254: v272.42,29.23 253.37,29.23 250.82,26.69 v247.01,26.69 v240.03,26.69 | IC42.6 250.19,20.34 251.46,21.61 262.89,21.61 264.16,20.34 IC43.6 | RF08B.11 224.16,132.09 224.79,132.73 231.78,132.73 232.41,133.36 236.85,133.36 238.12,132.09 IC39.6 250.19,132.09 251.46,133.36 269.24,133.36 270.51,132.09 IC45.6
DMA06  (via drill 0.61)  (1 unrouted)
  Top 0.254: E43.7 266.06,25.41 268.61,25.41 268.61,24.78 IC43.7 | v241.3,22.88 241.3,24.14 242.57,25.41 E42.7 | E45.7 267.33,137.17 269.88,137.17 269.88,136.54 IC45.7 | E39.7 244.47,137.17 247.01,137.17 247.01,136.54 IC39.7
  Bottom 0.254: RF08A.13 224.16,22.88 225.43,24.14 235.59,24.14 236.85,22.88 v241.3,22.88 IC42.7 252.73,22.88 254,24.14 267.97,24.14 269.24,22.88 IC43.7 | RF08B.13 224.16,134.63 225.43,135.9 235.59,135.9 236.22,135.27 248.28,135.27 IC39.7 254,134.63 255.27,135.9 269.24,135.9 270.51,134.63 IC45.7
DMA07  (via drill 0.61)  (1 unrouted)
  Top 0.254: E43.8 266.06,26.69 269.88,26.69 269.88,26.05 IC43.8 | v245.75,25.41 245.75,26.69 244.47,26.69 E42.8 | E45.8 267.33,138.44 271.14,138.44 271.14,137.81 IC45.8 | E39.8 244.47,138.44 248.28,138.44 248.28,137.81 IC39.8
  Bottom 0.254: RF08A.15 224.16,25.41 224.79,26.05 231.78,26.05 232.41,26.69 238.76,26.69 240.03,25.41 v245.75,25.41 IC42.8 250.82,25.41 252.09,26.69 256.54,26.69 257.18,26.05 268.61,26.05 269.24,25.41 IC43.8 | RF08B.15 224.16,137.17 224.79,137.81 231.78,137.81 232.41,138.44 240.03,138.44 241.3,137.17 IC39.8 250.82,137.17 252.09,138.44 269.24,138.44 270.51,137.17 IC45.8
DMA08  (via drill 0.61)  (1 unrouted)
  Top 0.254: IC42.9 244.47,27.96 E42.9 242.57,27.96 239.4,24.78 239.4,13.99 250.19,3.19 262.89,3.19 262.89,21.61 261.62,22.88 261.62,25.41 264.16,27.96 E43.9 266.06,27.96 IC43.9 | v227.97,40.66 226.06,38.75 226.06,34.3 222.88,34.3 222.25,33.67 222.25,29.86 223.52,28.59 RF08A.17 | E45.9 267.33,139.71 IC45.9 | E39.9 244.47,139.71 IC39.9
  Bottom 0.254: v227.97,40.66 229.24,41.92 245.11,41.92 247.65,44.47 263.52,44.47 268.61,39.38 271.78,39.38 273.69,37.48 273.69,27.96 IC43.9 | RF08B.17 224.16,139.71 225.43,140.98 243.21,140.98 244.47,139.71 IC39.9 250.19,139.71 251.46,140.98 269.24,140.98 270.51,139.71 IC45.9
DMA09  (via drill 0.61)  (1 unrouted)
  Top 0.254: E45.10 267.33,140.98 270.51,140.98 270.51,142.25 IC45.10 | E39.10 244.47,140.98 247.65,140.98 247.65,142.25 IC39.10 | 238.76,29.23 237.49,29.23 v237.49,28.59 | 238.76,29.23 242.57,29.23 E42.10 | v226.06,28.59 224.16,30.5 RF08A.19 | E43.10 266.06,29.23 269.24,29.23 269.24,30.5 IC43.10 | 238.76,29.23 v238.76,40.66
  Bottom 0.254: RF08B.19 231.14,142.25 232.41,143.52 240.03,143.52 240.66,142.89 248.28,142.89 IC39.10 251.46,142.25 252.73,143.52 257.81,143.52 259.08,142.25 IC45.10 | v237.49,28.59 236.85,29.23 226.69,29.23 v226.06,28.59 | IC42.10 250.19,30.5 250.82,31.13 253.37,31.13 254,31.77 258.44,31.77 259.71,30.5 IC43.10 271.14,31.13 272.42,31.13 272.42,36.21 271.78,36.84 269.24,36.84 264.16,41.92 247.65,41.92 247.01,41.29 239.4,41.29 v238.76,40.66
DMA10  (via drill 0.61)  (1 unrouted)
  Top 0.254: v262.89,31.77 262.89,30.5 264.16,30.5 E43.11 | v240.03,33.67 240.03,30.5 242.57,30.5 E42.11 | v264.16,143.52 264.16,142.25 265.43,142.25 E45.11 | v241.3,144.79 241.3,142.25 242.57,142.25 E39.11
  Bottom 0.254: IC43.11 264.16,33.04 v262.89,31.77 261.62,33.04 257.81,33.04 256.54,34.3 251.46,34.3 250.19,33.04 IC42.11 240.66,33.04 v240.03,33.67 239.4,34.3 225.43,34.3 224.16,33.04 RF08A.21 | IC45.11 265.43,144.79 v264.16,143.52 262.89,144.79 259.08,144.79 257.81,146.06 251.46,146.06 250.19,144.79 IC39.11 v241.3,144.79 240.03,146.06 225.43,146.06 224.16,144.79 RF08B.21
DMA11  (via drill 0.61)  (1 unrouted)
  Top 0.254: E45.12 267.33,143.52 269.88,143.52 269.88,145.43 IC45.12 | E39.12 244.47,143.52 247.01,143.52 247.01,145.43 IC39.12 | E43.12 266.06,31.77 268.61,31.77 268.61,33.67 IC43.12 | v245.75,34.3 245.75,31.77 244.47,31.77 E42.12
  Bottom 0.254: RF08B.23 224.16,147.33 225.43,148.6 246.38,148.6 247.65,147.33 IC39.12 250.82,147.33 252.09,148.6 269.24,148.6 270.51,147.33 IC45.12 | RF08A.23 224.16,35.58 224.79,36.21 231.78,36.21 232.41,36.84 243.21,36.84 v245.75,34.3 247.01,35.58 IC42.12 251.46,35.58 252.73,36.84 267.97,36.84 269.24,35.58 IC43.12
DRV01\  (1 unrouted)
  Bottom 0.254: JP1.3 226.06,54.62 222.88,54.62 221.62,53.36 RF08A.38 | JP2.3 226.06,166.38 222.88,166.38 221.62,165.11 RF08B.38
DRV23\  (1 unrouted)
  Top 0.254: JP1.1 233.68,55.9 227.33,49.55 227.33,42.56 224.16,39.38 222.25,39.38 222.25,34.94 220.98,33.67 RF08A.22
  Bottom 0.254: JP2.1 231.78,170.83 222.25,170.83 219.07,167.65 219.07,145.43 220.98,145.43 RF08B.22
DRVOK\  (1 unrouted)
  Top 0.254: RF08A.40 D4.A | RF08B.40 D8.A
DRVSELA\  (via drill 0.61)
  Top 0.254: v228.6,31.77 228.6,30.5 229.87,30.5 E42.22 | v247.01,31.77 250.19,31.77 250.82,31.13 250.82,30.5 251.46,30.5 E43.22 | R3.1 261.62,5.73 259.71,7.63 v259.71,31.77 259.71,51.45 IC44.4
  Bottom 0.254: v228.6,31.77 229.87,33.04 IC42.22 234.31,32.4 246.38,32.4 v247.01,31.77 252.73,31.77 254,33.04 IC43.22 256.54,33.04 257.18,32.4 259.08,32.4 v259.71,31.77 | IC44.4 254.63,60.34 254.63,69.86 220.98,69.86 D4.C
DRVSELB\  (via drill 0.61)
  Top 0.254: v228.6,143.52 228.6,142.25 229.87,142.25 E39.22 | v251.46,143.52 251.46,142.25 252.73,142.25 E45.22 | R4.1 264.16,117.49 261.62,120.03 v261.62,143.52 261.62,161.3 IC46.4
  Bottom 0.254: v228.6,143.52 229.87,144.79 IC39.22 234.95,144.79 235.59,144.16 240.66,144.16 241.3,143.52 v251.46,143.52 252.73,144.79 IC45.22 257.81,144.79 259.08,143.52 v261.62,143.52 | D8.C 226.06,177.81 240.03,177.81 243.84,174 247.65,174 251.46,170.19 IC46.4
GND  (via drill 0.61)  (1 unrouted)
  Top 0.254: RF08A.39 223.52,56.53 226.69,59.7 226.69,73.04 G1.- 234.31,81.93 234.31,83.2 G1.-@1 | G2.-@1 262.25,83.2 262.25,81.93 G2.- 262.25,80.66 262.25,75.58 IC44.7 249.56,62.88 249.56,46.37 IC42.16 | E43.16 266.06,36.84 266.7,37.48 266.7,39.38 269.24,41.92 272.42,41.92 272.42,43.83 IC43.16 | v245.11,43.2 245.11,37.48 244.47,36.84 E42.16 | 239.4,162.57 234.95,167.02 223.52,167.02 | 239.4,162.57 242.57,159.4 242.57,148.6 E39.16 | 223.52,167.02 222.25,165.75 222.25,159.4 223.52,158.13 RF08B.31 | 223.52,167.02 RF08B.39 | E45.16 267.33,148.6 267.97,149.24 267.97,151.14 270.51,153.68 273.69,153.68 273.69,155.59 IC45.16 | G4.-@1 262.25,194.96 262.25,193.69 G4.- 253.37,183.53 253.37,178.45 IC46.7 250.19,175.27 250.19,166.38 | G3.- 234.31,193.69 234.31,194.96 G3.-@1 | 250.19,166.38 250.19,158.76 IC39.16 | 239.4,162.57 243.21,166.38 250.19,166.38
  Bottom 0.254: 246.38,44.47 247.65,45.73 IC42.16 250.19,45.73 251.46,47.01 256.54,47.01 257.18,46.37 268.61,46.37 269.24,45.73 IC43.16 | 246.38,44.47 v245.11,43.2 | 246.38,44.47 232.41,44.47 231.78,45.1 224.79,45.1 224.16,45.73 RF08A.31 | G1.-@1 235.59,83.2 262.25,83.2 G2.-@1 | G3.- 250.19,177.81 IC46.7 | IC45.16 270.51,157.49 269.88,158.13 258.44,158.13 257.81,158.76 251.46,158.76 250.19,157.49 IC39.16
MEMSUPPLY  (1 unrouted)
  Top 0.508: E42.32 231.78,17.8 231.78,9.54 IC42.32 | D1.C 233.04,5.73 233.04,7 IC42.32 | E43.32 251.46,17.8 R3.2 | D2.C 236.22,10.18 IC42.32 | E39.32 231.78,129.55 231.78,121.3 IC39.32 233.04,118.76 233.04,117.49 D6.C 236.22,116.86 | 254,119.39 254,129.55 E45.32 | 254,119.39 R4.2 236.22,116.86 | 254,119.39 IC45.32 | 236.22,116.86 D5.C
  Bottom 0.508: D2.C 238.76,50.81 IC44.14 246.38,50.81 247.65,49.55 262.89,49.55 D3.C | IC43.32 252.73,5.09 R3.2 D1.C | D5.C 238.76,162.57 IC46.14 246.38,162.57 247.65,161.3 262.89,161.3 D7.C
N$1
  Top 0.254: E43.19 253.37,34.3 256.54,34.3 257.18,34.94 257.18,38.75 IC43.19
N$2  (via drill 0.61)
  Top 0.254: v247.01,36.84 247.01,34.3 250.19,34.3 250.82,33.67 250.82,33.04 251.46,33.04 E43.20
  Bottom 0.254: v247.01,36.84 251.46,36.84 252.73,38.12 IC43.20
N$3  (via drill 0.61)
  Top 0.254: v257.81,34.3 257.81,31.77 253.37,31.77 E43.21
  Bottom 0.254: v257.81,34.3 256.54,35.58 IC43.21
N$4
  Top 0.254: E45.19 254.63,146.06 257.81,146.06 258.44,146.7 258.44,150.51 IC45.19
N$5  (via drill 0.61)
  Top 0.254: v250.82,148.6 250.82,144.79 252.73,144.79 E45.20
  Bottom 0.254: v250.82,148.6 252.09,149.88 IC45.20
N$6  (via drill 0.61)
  Top 0.254: v259.08,146.06 259.08,143.52 254.63,143.52 E45.21
  Bottom 0.254: v259.08,146.06 257.81,147.33 IC45.21
N$18
  Top 0.254: IC44.3 250.82,57.8 250.82,59.07 IC44.5 252.09,61.61 252.09,62.88 IC44.6
N$35
  Top 0.254: IC44.1 252.09,51.45 252.09,52.72 IC44.2
  Bottom 0.254: JP1.2 233.68,54.62 250.19,54.62 251.46,53.36 IC44.2
N$36
  Top 0.254: D7.A G4.+@1 267.33,173.37 267.33,174.64 G4.+@2 | G4.+ 258.44,173.37 258.44,174.64 G4.+@3
  Bottom 0.254: G4.+ 260.35,174 261.62,174 G4.+@4 264.16,174 265.43,174 G4.+@1
N$38
  Top 0.254: IC46.3 250.82,169.56 250.82,170.83 IC46.5 252.09,173.37 252.09,174.64 IC46.6
N$39
  Top 0.254: IC46.1 252.09,163.21 252.09,164.48 IC46.2
  Bottom 0.254: JP2.2 233.68,166.38 250.19,166.38 251.46,165.11 IC46.2
N$41
  Top 0.254: D5.A G3.+@1 239.4,173.37 239.4,174.64 G3.+@2 | G3.+ 230.5,173.37 230.5,174.64 G3.+@3
  Bottom 0.254: G3.+ 232.41,174 233.68,174 G3.+@4 236.22,174 237.49,174 G3.+@1
N$130
  Top 0.254: D3.A G2.+@1 267.33,61.61 267.33,62.88 G2.+@2 | G2.+ 258.44,61.61 258.44,62.88 G2.+@3
  Bottom 0.254: G2.+ 260.35,62.24 261.62,62.24 G2.+@4 264.16,62.24 265.43,62.24 G2.+@1
N$131
  Top 0.254: D2.A G1.+@1 239.4,61.61 239.4,62.88 G1.+@2 | G1.+ 230.5,61.61 230.5,62.88 G1.+@3
  Bottom 0.254: G1.+ 232.41,62.24 233.68,62.24 G1.+@4 236.22,62.24 237.49,62.24 G1.+@1
VCC  (1 unrouted)
  Top 0.508: D6.A 222.25,116.86 220.98,118.12 RF08B.2 | D1.A 222.25,5.09 220.98,6.36 RF08A.2
WE\  (via drill 0.61)  (1 unrouted)
  Top 0.254: E43.29 253.37,21.61 257.18,21.61 257.18,20.34 258.44,19.07 258.44,10.81 256.54,8.91 253.37,8.91 253.37,13.35 IC43.29 | v227.97,15.26 227.97,19.7 229.87,21.61 E42.29 | E45.29 254.63,133.36 258.44,133.36 258.44,131.46 259.08,130.82 259.08,121.94 257.81,120.67 254.63,120.67 254.63,125.11 IC45.29 | E39.29 229.87,133.36 224.79,128.28 220.98,128.28 RF08B.8
  Bottom 0.254: RF08A.8 221.62,15.26 222.88,13.99 224.16,13.99 225.43,15.26 v227.97,15.26 IC42.29 235.59,15.26 236.85,13.99 250.19,13.99 250.82,14.62 253.37,14.62 254,15.26 IC43.29 | RF08B.8 221.62,127.02 222.88,125.75 224.16,125.75 224.79,126.38 231.78,126.38 232.41,127.02 IC39.29 245.11,127.02 246.38,125.75 250.19,125.75 250.82,126.38 254.63,126.38 255.27,127.02 IC45.29
WRITING  (via drill 0.61)  (1 unrouted)
  Top 0.254: E43.24 253.37,27.96 IC43.24 | E42.24 231.78,27.96 IC42.24 | v229.24,3.83 224.16,8.91 219.71,8.91 219.71,26.05 220.98,27.32 RF08A.18 | E45.24 254.63,139.71 IC45.24 260.99,135.27 260.99,121.3 255.27,115.58 225.43,115.58 225.43,121.94 224.16,123.2 219.71,123.2 219.71,137.81 220.98,139.08 RF08B.18 | E39.24 231.78,139.71 IC39.24
  Bottom 0.254: RF08A.18 221.62,27.96 222.88,26.69 231.14,26.69 232.41,27.96 IC42.24 | v229.24,3.83 269.24,3.83 272.42,7 273.05,7 273.05,25.41 271.78,26.69 257.81,26.69 256.54,27.96 IC43.24 | RF08B.18 221.62,139.71 222.88,138.44 231.14,138.44 232.41,139.71 IC39.24

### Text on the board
Bottom: RS08 | VRS | RF08 Debug | VRS | RS08 | VRS | RF08 | VRS
tPlace: RF08 | VRS
tValues: RF08 Debug | VRS | RS08 | VRS | RS08 | VRS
